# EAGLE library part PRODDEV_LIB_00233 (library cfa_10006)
CFAG12864K
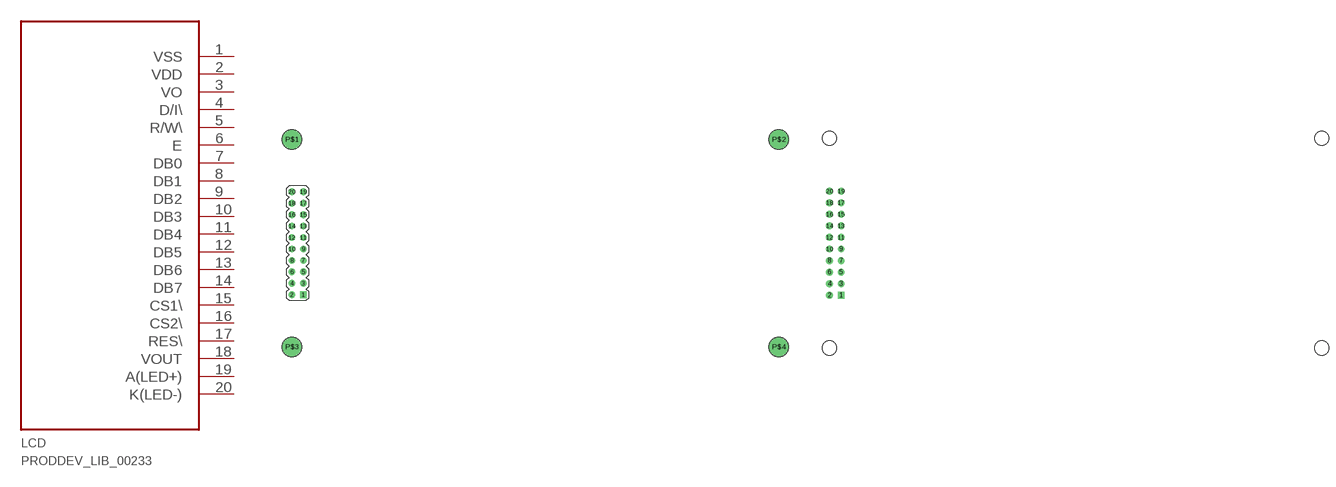
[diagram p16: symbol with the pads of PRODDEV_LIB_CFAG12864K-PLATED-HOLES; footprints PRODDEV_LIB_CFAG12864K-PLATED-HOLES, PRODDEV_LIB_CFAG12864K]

Designator prefix LCD

## PRODDEV_LIB_00233  [PRODDEV_LIB_CFAG12864K-PLATED-HOLES]
1  VSS  pwr
2  VDD  pwr
3  VO  pas
4  D/I\  in
5  R/W\  in
6  E  in
7  DB0  in
8  DB1
9  DB2
10  DB3
11  DB4
12  DB5
13  DB6
14  DB7
15  CS1\  in
16  CS2\  in
17  RES\  in
18  VOUT  pas
19  A(LED+)  pas
20  K(LED-)  pas

## PRODDEV_LIB_00233NON-PLATED-HOLES  [PRODDEV_LIB_CFAG12864K]
Pads as for PRODDEV_LIB_CFAG12864K-PLATED-HOLES

## Footprint PRODDEV_LIB_CFAG12864K-PLATED-HOLES (pad centres in mm)
drill 1 square: 1 0,0
drill 1 round: 2 -2.54,0; 3 0,2.54; 4 -2.54,2.54; 5 0,5.08; 6 -2.54,5.08; 7 0,7.62; 8 -2.54,7.62; 9 0,10.16; 10 -2.54,10.16; 11 0,12.7; 12 -2.54,12.7; 13 0,15.24; 14 -2.54,15.24; 15 0,17.78; 16 -2.54,17.78; 17 0,20.32; 18 -2.54,20.32; 19 0,22.86; 20 -2.54,22.86
drill 3.1 round: P$1 -2.54,34.43; P$2 105.46,34.43; P$3 -2.54,-11.57; P$4 105.46,-11.57

## Footprint PRODDEV_LIB_CFAG12864K (pad centres in mm)
drill 1 square: 1 0,0
drill 1 round: 2 -2.54,0; 3 0,2.54; 4 -2.54,2.54; 5 0,5.08; 6 -2.54,5.08; 7 0,7.62; 8 -2.54,7.62; 9 0,10.16; 10 -2.54,10.16; 11 0,12.7; 12 -2.54,12.7; 13 0,15.24; 14 -2.54,15.24; 15 0,17.78; 16 -2.54,17.78; 17 0,20.32; 18 -2.54,20.32; 19 0,22.86; 20 -2.54,22.86
hole 3.1 at -2.54,34.43
hole 3.1 at 105.46,34.43
hole 3.1 at -2.54,-11.57
hole 3.1 at 105.46,-11.57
